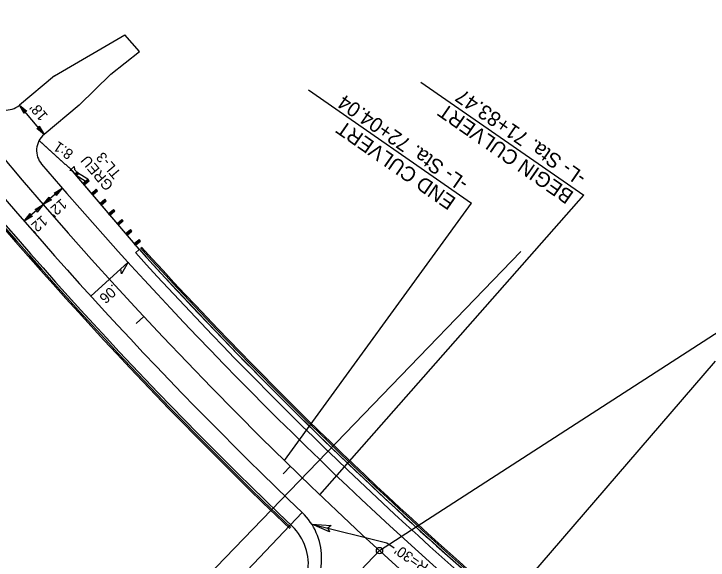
# Model space of a CAD drawing. Extents: x 472216 to 481979, y 489069 to 507339.
# Drawn here: x 478893 to 479224, y 493958.2 to 494218.7 of the extents above; entities that cross this region are included whole.
import ezdxf

# ---------------------------------------------------------------- set-up
doc = ezdxf.new("R2010")
doc.units = 0
for name, color, linetype in [('Old_Level_12', 7, 'Continuous'), ('Prop Drainage Structure Drop Inlet Grate 2 Narrow Slots and Sag Grates 840 24 CELL', 7, 'Continuous'), ('Prop Drainage Structure Drop Inlet Grate 2 Wide Slots and Sag Grates 840 22 Label', 7, 'Continuous'), ('Prop Drainage Structure Outlet Berm Ditch 850 10 CELL', 7, 'Continuous'), ('Prop Drainage Structure Pipe CSP 15in', 7, 'Continuous'), ('Prop Drainage Structure Pipe Plug CELL', 7, 'Continuous'), ('Prop Drainage Structure Pipe RCP 24in Class III Label', 7, 'Continuous'), ('Prop Drainage Structure Tops and Inverts LABEL', 7, 'Continuous'), ('Prop Earthen Structure False Sump CELL', 7, 'Continuous'), ('Prop Erosion Embankment Toe Protection CELL', 7, 'Continuous'), ('Sheet Block Revision CELL', 7, 'Continuous'), ('Sheet Block Title CELL', 7, 'Continuous'), ('Sheet North Arrow Point CELL', 7, 'Continuous'), ('Sheet PE Seal Cell', 7, 'Continuous'), ('Sheet Plot Border Outside CELL', 7, 'Continuous')]:
    doc.layers.add(name, color=color, linetype=linetype)

msp = doc.modelspace()

# ---------------------------------------------------------------- linework, layer by layer
at = {"layer": 'Old_Level_12'}
for p, q in [((479086.98, 494186.18), (479164.78, 494132.21)), ((479033.43, 494182.43), (479111.23, 494128.46)), ((479038.91, 493989.39), (479164.78, 494132.21)), ((479021.94, 494005.79), (479111.23, 494128.46)), ((479067.26, 493962.77), (479252.87, 494082.72))]:
    msp.add_line(p, q, dxfattribs=at)
msp.add_circle((479067.3, 493962.79), 1.5, dxfattribs=at)
at = {"layer": 'Prop Drainage Structure Drop Inlet Grate 2 Narrow Slots and Sag Grates 840 24 CELL'}
msp.add_lwpolyline([(478947.42, 494100.29), (478944.33, 494094.77), (478944, 494097.18)], close=True, dxfattribs=at)
at = {"layer": 'Prop Drainage Structure Drop Inlet Grate 2 Wide Slots and Sag Grates 840 22 Label'}
msp.add_line((478929.67, 494084.14), (478947.42, 494100.29), dxfattribs=at)
at = {"layer": 'Prop Drainage Structure Outlet Berm Ditch 850 10 CELL'}
for points in [[(478897.92, 494171.23), (478895.62, 494175.18), (478899.14, 494172.22), (478898.16, 494172.15)], [(478905.1, 494165.09), (478907.4, 494161.14), (478903.87, 494164.09), (478904.86, 494164.17)], [(478912.13, 494133.23), (478916.04, 494135.6), (478913.15, 494132.02), (478913.06, 494133.01)], [(478910.88, 494130.09), (478906.98, 494127.73), (478909.87, 494131.3), (478909.96, 494130.32)], [(478903.07, 494125.36), (478906.98, 494127.73), (478904.09, 494124.16), (478904, 494125.14)], [(478901.82, 494122.22), (478897.92, 494119.86), (478900.81, 494123.43), (478900.9, 494122.45)], [(479043.39, 493971.66), (479035.02, 493975.32), (479044.19, 493974.71), (479042.69, 493973.43)]]:
    msp.add_lwpolyline(points, close=True, dxfattribs=at)
at = {"layer": 'Prop Drainage Structure Pipe Plug CELL'}
for p, q in [((478919.61, 494143.93), (478921.81, 494145.88)), ((478921.81, 494145.88), (478921.95, 494144.43)), ((478921.03, 494143.62), (478919.61, 494143.93)), ((478922.39, 494142.09), (478921.03, 494143.62)), ((478921.95, 494144.43), (478923.3, 494142.89)), ((478922.03, 494142.39), (478923.17, 494143.36)), ((478922.03, 494142.39), (478923.82, 494142.6)), ((478922.85, 494142.49), (478922.39, 494142.09)), ((478923.17, 494143.36), (478922.67, 494141.63)), ((478922.67, 494141.63), (478923.82, 494142.6)), ((478923.3, 494142.89), (478922.85, 494142.49)), ((478923.82, 494142.6), (478923.17, 494143.36)), ((478923.82, 494142.6), (478923.49, 494142.98)), ((478928.18, 494139.89), (478923.82, 494142.6)), ((478952.66, 494106.42), (478922.35, 494142.01)), ((478927.02, 494138.89), (478922.67, 494141.63)), ((478925.85, 494137.9), (478928.18, 494139.89)), ((478926.5, 494137.14), (478928.83, 494139.12)), ((478927.02, 494138.89), (478928.83, 494139.12)), ((478928.18, 494139.89), (478927.67, 494138.13)), ((478928.83, 494139.12), (478928.18, 494139.89)), ((478927.67, 494138.13), (478925.85, 494137.9)), ((478926.5, 494137.14), (478927.02, 494138.89)), ((478927.67, 494138.13), (478927.02, 494138.89)), ((478929.94, 494133.1), (478932.22, 494135.05)), ((478931.73, 494133.31), (478929.94, 494133.1)), ((478930.59, 494132.34), (478932.87, 494134.29)), ((478930.59, 494132.34), (478931.08, 494134.07)), ((478931.08, 494134.07), (478932.87, 494134.29)), ((478931.73, 494133.31), (478931.08, 494134.07)), ((478932.22, 494135.05), (478931.73, 494133.31)), ((478932.87, 494134.29), (478932.22, 494135.05)), ((478934.02, 494128.3), (478936.41, 494130.34)), ((478934.67, 494127.54), (478937.06, 494129.58)), ((478934.67, 494127.54), (478935.22, 494129.32)), ((478935.22, 494129.32), (478937.06, 494129.58)), ((478935.87, 494128.56), (478935.22, 494129.32)), ((478936.41, 494130.34), (478935.87, 494128.56)), ((478937.06, 494129.58), (478936.41, 494130.34)), ((478935.87, 494128.56), (478934.02, 494128.3)), ((478938.11, 494123.51), (478940.42, 494125.48)), ((478939.91, 494123.73), (478938.11, 494123.51)), ((478938.76, 494122.75), (478938.11, 494123.51)), ((478938.76, 494122.75), (478941.07, 494124.71)), ((478938.76, 494122.75), (478939.26, 494124.49)), ((478939.26, 494124.49), (478941.07, 494124.71)), ((478939.91, 494123.73), (478939.26, 494124.49)), ((478940.42, 494125.48), (478939.91, 494123.73)), ((478941.07, 494124.71), (478940.42, 494125.48)), ((478942.19, 494118.71), (478944.51, 494120.69)), ((478942.84, 494117.95), (478945.16, 494119.92)), ((478942.84, 494117.95), (478943.35, 494119.7)), ((478943.35, 494119.7), (478945.16, 494119.92)), ((478944, 494118.94), (478943.35, 494119.7)), ((478944.51, 494120.69), (478944, 494118.94)), ((478945.16, 494119.92), (478944.51, 494120.69)), ((478944, 494118.94), (478942.19, 494118.71)), ((478946.28, 494113.91), (478948.6, 494115.89)), ((478948.6, 494115.89), (478948.09, 494114.14)), ((478949.25, 494115.13), (478948.6, 494115.89)), ((478948.09, 494114.14), (478946.28, 494113.91)), ((478946.93, 494113.15), (478949.25, 494115.13)), ((478946.93, 494113.15), (478947.44, 494114.9)), ((478947.44, 494114.9), (478949.25, 494115.13)), ((478948.09, 494114.14), (478947.44, 494114.9)), ((478950.37, 494109.12), (478952.65, 494111.06)), ((478950.37, 494109.12), (478951.51, 494110.09)), ((478952.16, 494109.33), (478950.37, 494109.12)), ((478951.01, 494108.35), (478953.3, 494110.3)), ((478951.51, 494110.09), (478951.01, 494108.35)), ((478951.51, 494110.09), (478953.3, 494110.3)), ((478952.16, 494109.33), (478951.51, 494110.09)), ((478952.65, 494111.06), (478952.16, 494109.33)), ((478953.3, 494110.3), (478952.65, 494111.06)), ((478951.01, 494108.35), (478950.37, 494109.12))]:
    msp.add_line(p, q, dxfattribs=at)
at = {"layer": 'Prop Drainage Structure Pipe RCP 24in Class III Label'}
for p, q in [((478912.33, 494189.2), (478945.88, 494208.74)), ((478952.82, 494200.81), (478945.88, 494208.74)), ((478939.21, 494189.87), (478952.82, 494200.81)), ((478912.33, 494189.2), (478895.62, 494175.18)), ((478924.11, 494175.17), (478939.21, 494189.87)), ((478924.11, 494175.17), (478907.4, 494161.14)), ((478951.05, 494104.72), (478952.78, 494106.29))]:
    msp.add_line(p, q, dxfattribs=at)
for centre, radius, start, end in [((480454.83, 495471.85), 2062, 210.38827, 226.30878), ((478889.19, 494182.84), 10, 219.465, 310.0064), ((478913.82, 494153.48), 10, 130.0064, 220.5478), ((480454.83, 495471.85), 2038, 220.54778, 237.1188), ((479009.73, 493959.18), 30, 316.135, 46.3088)]:
    msp.add_arc(centre, radius, start, end, dxfattribs=at)
at = {"layer": 'Prop Drainage Structure Tops and Inverts LABEL'}
for centre, radius, start, end in [((480454.83, 495471.85), 2070, 210.39099, 226.33588), ((480454.83, 495471.85), 2030, 222.26999, 236.02944), ((479008.38, 493956.32), 25, 295.2311, 46.3359)]:
    msp.add_arc(centre, radius, start, end, dxfattribs=at)
at = {"layer": 'Prop Earthen Structure False Sump CELL'}
msp.add_arc((480454.83, 495471.85), 2032.33, 222.27482, 236.02863, dxfattribs=at)
at = {"layer": 'Prop Erosion Embankment Toe Protection CELL'}
msp.add_line((478952.66, 494106.42), (478920.24, 494144.49), dxfattribs=at)
for centre, radius, start, end in [((480454.83, 495471.85), 2070, 210.39099, 226.33588), ((480454.83, 495471.85), 2030, 222.26999, 231.79579), ((480454.83, 495471.85), 2030, 222.26999, 236.02944), ((479008.38, 493956.32), 25, 295.3548, 46.3359)]:
    msp.add_arc(centre, radius, start, end, dxfattribs=at)
msp.add_spline([(478920.24, 494144.49), (478919.92, 494144.77), (478919.6, 494145.06), (478919.28, 494145.35), (478918.96, 494145.64), (478918.64, 494145.93), (478918.32, 494146.22), (478918, 494146.51), (478917.68, 494146.79), (478917.36, 494147.08), (478917.04, 494147.37), (478916.72, 494147.66), (478916.4, 494147.95), (478916.08, 494148.24), (478915.76, 494148.53), (478915.44, 494148.82), (478915.12, 494149.11), (478914.8, 494149.4), (478914.48, 494149.69), (478914.16, 494149.98), (478913.84, 494150.27), (478913.52, 494150.56), (478913.2, 494150.85), (478912.88, 494151.14), (478912.56, 494151.43), (478912.24, 494151.72), (478911.92, 494152.01), (478911.6, 494152.3), (478911.28, 494152.59), (478910.96, 494152.88), (478910.64, 494153.17), (478910.32, 494153.46), (478910, 494153.75), (478909.68, 494154.04), (478909.36, 494154.33), (478909.05, 494154.62), (478908.73, 494154.92), (478908.41, 494155.21), (478908.09, 494155.5), (478907.77, 494155.79), (478907.45, 494156.08), (478907.13, 494156.37), (478906.81, 494156.66), (478906.5, 494156.96), (478906.18, 494157.25), (478905.86, 494157.54), (478905.54, 494157.83), (478905.22, 494158.12), (478905.05, 494158.28)], degree=3, dxfattribs=at)
at = {"layer": 'Sheet Block Revision CELL'}
for p, q in [((478907.4, 494161.14), (478895.62, 494175.18)), ((478916.04, 494135.6), (478897.92, 494119.86)), ((479127.54, 493936.98), (479227.42, 494053.08)), ((479030.46, 493980.87), (478986.49, 493934.85)), ((479035.02, 493975.32), (479070.73, 493966.52)), ((479070.73, 493966.52), (479074.25, 493964.07))]:
    msp.add_line(p, q, dxfattribs=at)
at = {"layer": 'Sheet Block Title CELL'}
msp.add_line((478926.28, 493889.59), (479134.72, 494105.35), dxfattribs=at)
at = {"layer": 'Sheet North Arrow Point CELL'}
msp.add_line((479019.2, 493912.74), (479067.3, 493962.79), dxfattribs=at)
msp.add_arc((480454.83, 495471.85), 2050, 189.81618, 250.32977, dxfattribs=at)
at = {"layer": 'Sheet PE Seal Cell'}
for p, q in [((478954.91, 494074.44), (478951.25, 494071.03)), ((479024.83, 494002.97), (479021.34, 493999.38))]:
    msp.add_line(p, q, dxfattribs=at)
at = {"layer": 'Sheet Plot Border Outside CELL'}
for radius, start, end in [(2071.6, 210.39099, 226.33588), (2070.94, 210.39099, 226.33588), (2029.06, 222.26999, 236.02944), (2028.4, 222.26999, 236.02944)]:
    msp.add_arc((480454.83, 495471.85), radius, start, end, dxfattribs=at)

# ---------------------------------------------------------------- texts
at = {"layer": 'Old_Level_12'}
for s, p in [('-L- Sta. 72+04.04', (479110.23, 494139.13)), ('-L- Sta. 71+83.47', (479166.4, 494141.97)), ('BEGIN CULVERT', (479160.42, 494133.34)), ('END CULVERT', (479104.25, 494130.5))]:
    msp.add_text(s, height=7, rotation=145.2516, dxfattribs=at).set_placement(p)
at = {"layer": 'Prop Drainage Structure Drop Inlet Grate 2 Narrow Slots and Sag Grates 840 24 CELL'}
msp.add_text('.06', height=5, rotation=222.2984, dxfattribs=at).set_placement((478940.17, 494090.07))
at = {"layer": 'Prop Drainage Structure Pipe CSP 15in'}
for s, rotation, p in [("18'", 130.0064, (478909.5, 494170.2)), ('8:1', 145.8471, (478921.79, 494152.95)), ("12'", 220.9727, (478915.64, 494130.91)), ("12'", 220.9727, (478906.43, 494122.91)), ("R=30'", 145.2516, (479091.09, 493955.87))]:
    msp.add_text(s, height=5, rotation=rotation, dxfattribs=at).set_placement(p)
at = {"layer": 'Prop Drainage Structure Pipe Plug CELL'}
for s, p in [('TL-3', (478944.48, 494142.75)), ('GREU', (478940.74, 494137.03))]:
    msp.add_text(s, height=5, rotation=130.3594, dxfattribs=at).set_placement(p)

doc.saveas('drawing.dxf')
